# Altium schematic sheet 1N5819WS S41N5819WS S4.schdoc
size 127 x 101 mm
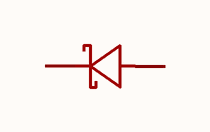
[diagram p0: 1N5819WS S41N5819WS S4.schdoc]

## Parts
D?  1n5819ws s4_c2927280  [SOD-323_L1.6-W1.3-LS2.7-RD]  (value not drawn)

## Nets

Not connected (* = marked no-connect by the designer): D? 1(C) 2(A)

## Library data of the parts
D? = 1n5819ws s4_c2927280: 二极管配置:独立式;正向压降(Vf):600mV@200mA;直流反向耐压(Vr):40V;整流电流:350mA;; Manufacturer: JSMSEMI(杰盛微); AddInBom: yes; ModelId: 39bca86493a8419684ee2090e9340edf; ModelTransform: 104.3305,51.181,0,0,0,0,0,0,0; Diode Configuration: 独立式; Voltage - DC Reverse(Vr): 40V; Current - Rectified: 350mA; Reverse Leakage Current (Ir): 5uA@30V; Non-Repetitive Peak Forward Surge Current: 1.5A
